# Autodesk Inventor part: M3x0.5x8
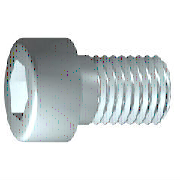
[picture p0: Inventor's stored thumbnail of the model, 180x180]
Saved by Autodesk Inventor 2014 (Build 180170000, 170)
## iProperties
IsCustomPart: 1
Company: 한국ATC센터
Created: 2009-02
Part Number: M3x0.5x8
Material: 강, 연강
Description: 6각머리 태핑 나사
Document SubType Name: Modeling
Standard: KS B 1003
Designer: KYOUNG IL JANG
Standards Organization: KS
Language: ko-KR
Size Designation: M 4 x 12
Categories: <MemberInstance><Categories><Category DisplayName="조임쇠" InternalName="e4da775c-781d-43d5-af7c-5136215cf5a6" Mnemonic="FSTN"><Category DisplayName="볼트" InternalN
Density: 7.86 g/cm^3
Mass: 1.37432 g
Surface Area: 2.584 cm^2
Volume: 0.174849 cm^3
Vendor: CBT Solutions
Appearance: 강철
Author: KYOUNG IL JANG
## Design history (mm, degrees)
sketch "스케치1"
  geometry: L1 (-0.867, 0)-(16, 0); L2 (16, 0)-(16, 1.5); L3 (16, 1.5)-(1.25, 1.5); L4 (1.25, 1.5)-(0.943, 1.5); L5 (0.943, 1.5)-(0, 1.5); L6 (0, 1.5)-(0, 2.75); L7 (0, 2.75)-(-3, 2.75); L8 (-3, 2.75)-(-3, 1.443); L9 (-3, 1.443)-(-1.7, 1.443); L10 (-1.7, 1.443)-(-0.867, 0); L11 (-6.8, 0)-(19.8, 0) reference; L12 (0, -0.55)-(0, 3.3) reference; L13 (1.25, 1.5)-(0, 1.5)
  constraints: 22 end point, 6 parallel, 2 collinear, 2 perpendicular, 1 horizontal, 1 point on line
  dimensions: "d1" = 14.75 distance from line of L3.end L2 (= GEL); "d2" = 0.30683 distance of L4.end L3.end (computed from GAL); "d3" = 3 distance between parallel lines of L8 L6 (= KOH); "d4" = 1.3 distance of L8.end L9.end (= INTI); "d5" = 60 deg angle of L10 L1; "d6" = 3 diameter of L3 L1 (= GD); "d7" = 3 diameter of L5 L1 (= BDM); "d8" = 2.88675 diameter of L9 L1 (= 1.1547 x SW); "d9" = 5.5 diameter of L7 L1 (= KOD); "d26" = 16 distance between parallel lines of L12 L2 (= NLG)
revolve "본체" sketch "스케치1" stored, may be unused: angle "d10" = 90 deg
sketch "스케치2"
  geometry: L1 (0, -3.85)-(0, 3.85) reference; L2 (-3.85, 0)-(3.85, 0) reference; L3 (1.443, 0)-(0.722, -1.25); L4 (0.722, -1.25)-(-0.722, -1.25); L5 (-0.722, -1.25)-(-1.443, 0); L6 (-1.443, 0)-(-0.722, 1.25); L7 (-0.722, 1.25)-(0.722, 1.25); L8 (0.722, 1.25)-(1.443, 0); 2 further points
  constraints: 12 end point, 1 coincident, 1 horizontal alignment, 1 point on line, 12 other
extrude "슬롯" join sketch "스케치2" stored distance "d11" = 10; taper "d12" = 0 deg
workplane "Work Plane1"
fillet "Fillet2" dims "d30" = 0.1 (= R)
body "Solid1"
fillet "모깎기1" dims "d17" = 0.3 (= RR)
feature "스레드" dims "d13" = 14.75 (= GEL), "d14" = 0
chamfer "모따기1" distance "d15" = 0.30673 (= -0.5 x SPD + 0.5 x GD); stored, may be unused: second distance "d16" = 0.30673 (= GUL), angle "d27" = 45 deg
other parameters: "GD" = 3 (= NND) [user parameter; used in 2 equation terms], "NLG" = 16 [user parameter; used in 1 equation term], "GEL" = 14.75 [user parameter; used in 2 equation terms], "KOD" = 5.5 [user parameter; used in 1 equation term], "KOH" = 3 [user parameter; used in 1 equation term], "INTI" = 1.3 [user parameter; used in 1 equation term], "GAL" = 0.30673 (= 0.61345 x PTC) [user parameter; used in 1 equation term], "GUL" = 0.30673 (= 0.61345 x PTC) [user parameter; used in 1 equation term], "BDM" = 3 (= NND) [user parameter; used in 1 equation term], "SW" = 2.5 [user parameter; used in 2 equation terms], "RR" = 0.3 [user parameter; used in 1 equation term], "SPD" = 2.38655 (= NND - 1.2269 x PTC) [user parameter; used in 1 equation term], "d19" = 0, "d28" = 0, "d29" = 0, "R" = 0.1 [user parameter; used in 1 equation term], "PHH" = 0.1 [user parameter], "GD1" = 2.38655 (= THREADDIA - 1.2269 x PTC) [user parameter], "THREADDIA" = 3 [user parameter; used in 1 equation term], "FAWI" = 45 deg [user parameter], "PTC" = 0.5 [user parameter; used in 5 equation terms], "NND" = 3 [user parameter; used in 3 equation terms], "TOA" = 30 deg [user parameter], "E0" = 2.8875 (= 1.155 x SW) [user parameter]
